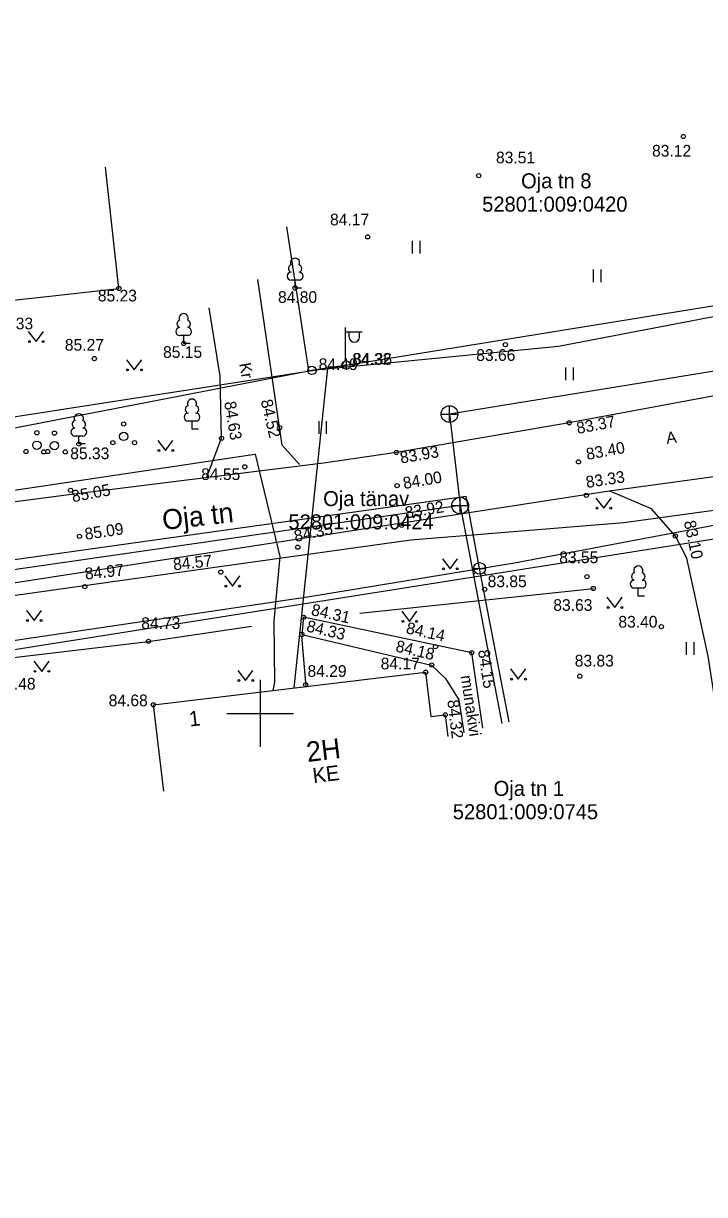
# Model space of a CAD drawing. Extents: x 648748 to 649126, y 6457789 to 6458252.
# Drawn here: x 649035.8 to 649076.6, y 6458121.2 to 6458191.3 of the extents above; entities that cross this region are included whole.
import ezdxf

# ---------------------------------------------------------------- set-up
doc = ezdxf.new("R2010")
doc.units = 0
for name, color, linetype in [('AED', 7, 'Continuous'), ('HALJASTUS', 7, 'Continuous'), ('HOONE', 7, 'Continuous'), ('KKAEV', 7, 'Continuous'), ('KORGUS-EH2000', 7, 'Continuous'), ('KTRASS', 7, 'Continuous'), ('MPOHULIIN', 7, 'Continuous'), ('PIIR', 7, 'Continuous'), ('POST', 7, 'Continuous'), ('PUU', 7, 'Continuous'), ('SITRASS', 7, 'Continuous'), ('SKTRASS', 7, 'Continuous'), ('TEE', 7, 'Continuous'), ('VKAEV', 7, 'Continuous'), ('VORK', 7, 'Continuous'), ('VTRASS', 7, 'Continuous')]:
    doc.layers.add(name, color=color, linetype=linetype)

msp = doc.modelspace()

# ---------------------------------------------------------------- linework, layer by layer
at = {"layer": 'AED'}
msp.add_line((649052.469, 6458154.613), (649052.733, 6458151.606), dxfattribs=at)
at = {"layer": 'HALJASTUS'}
for p, q in [((649059.114, 6458178.281), (649059.114, 6458177.52)), ((649059.569, 6458178.281), (649059.569, 6458177.52)), ((649069.949, 6458176.567), (649069.949, 6458175.806)), ((649070.404, 6458176.567), (649070.404, 6458175.806)), ((649036.117, 6458172.858), (649036.58, 6458172.252)), ((649036.58, 6458172.252), (649037.026, 6458172.858)), ((649042, 6458171.165), (649042.463, 6458170.558)), ((649042.463, 6458170.558), (649042.909, 6458171.165)), ((649068.287, 6458170.699), (649068.287, 6458169.938)), ((649068.742, 6458170.699), (649068.742, 6458169.938)), ((649053.508, 6458167.495), (649053.508, 6458166.734)), ((649053.963, 6458167.495), (649053.963, 6458166.734)), ((649043.871, 6458166.341), (649044.335, 6458165.734)), ((649044.335, 6458165.734), (649044.78, 6458166.341)), ((649070.112, 6458162.887), (649070.575, 6458162.281)), ((649070.575, 6458162.281), (649071.021, 6458162.887)), ((649060.913, 6458159.257), (649061.377, 6458158.651)), ((649061.377, 6458158.651), (649061.822, 6458159.257)), ((649047.879, 6458158.226), (649048.342, 6458157.619)), ((649048.342, 6458157.619), (649048.788, 6458158.226)), ((649055.967, 6458155.997), (649069.954, 6458157.476)), ((649070.772, 6458156.947), (649071.235, 6458156.341)), ((649071.235, 6458156.341), (649071.681, 6458156.947)), ((649035.999, 6458156.164), (649036.463, 6458155.557)), ((649036.463, 6458155.557), (649036.908, 6458156.164)), ((649058.48, 6458156.113), (649058.943, 6458155.506)), ((649058.943, 6458155.506), (649059.389, 6458156.113)), ((649075.514, 6458154.267), (649075.514, 6458153.506)), ((649075.969, 6458154.267), (649075.969, 6458153.506)), ((649036.454, 6458153.122), (649036.918, 6458152.516)), ((649036.918, 6458152.516), (649037.363, 6458153.122)), ((649048.663, 6458152.575), (649049.126, 6458151.968)), ((649049.126, 6458151.968), (649049.572, 6458152.575)), ((649064.997, 6458152.657), (649065.461, 6458152.051)), ((649065.461, 6458152.051), (649065.906, 6458152.657))]:
    msp.add_line(p, q, dxfattribs=at)
msp.add_lwpolyline([(649033.987, 6458147.007), (649033.538, 6458153.135), (649043.314, 6458154.31), (649049.482, 6458155.214)], dxfattribs=at)
for centre in [(649036.179, 6458172.252), (649037.008, 6458172.252), (649042.062, 6458170.558), (649042.891, 6458170.558), (649043.934, 6458165.734), (649044.763, 6458165.734), (649070.174, 6458162.281), (649071.003, 6458162.281), (649060.976, 6458158.651), (649061.805, 6458158.651), (649047.941, 6458157.619), (649048.77, 6458157.619), (649070.834, 6458156.341), (649071.663, 6458156.341), (649036.062, 6458155.557), (649036.891, 6458155.557), (649058.542, 6458155.506), (649059.371, 6458155.506), (649036.517, 6458152.516), (649037.346, 6458152.516), (649048.725, 6458151.968), (649049.554, 6458151.968), (649065.06, 6458152.051), (649065.889, 6458152.051)]:
    msp.add_circle(centre, 0.055, dxfattribs=at)
at = {"layer": 'HOONE'}
for points in [[(649023.87, 6458175.039), (649024.058, 6458173.502), (649041.542, 6458175.437), (649040.739, 6458182.695)], [(649044.224, 6458145.349), (649043.606, 6458150.514), (649059.909, 6458152.464), (649060.223, 6458149.811), (649061.086, 6458149.913), (649061.239, 6458148.619)]]:
    msp.add_lwpolyline(points, dxfattribs=at)
at = {"layer": 'KKAEV'}
for p, q in [((649060.837, 6458167.918), (649061.837, 6458167.918)), ((649061.337, 6458167.418), (649061.337, 6458168.418)), ((649061.979, 6458161.936), (649061.979, 6458162.936)), ((649061.479, 6458162.436), (649062.479, 6458162.436))]:
    msp.add_line(p, q, dxfattribs=at)
for centre in [(649061.337, 6458167.918), (649061.979, 6458162.436)]:
    msp.add_circle(centre, 0.5, dxfattribs=at)
at = {"layer": 'KORGUS-EH2000'}
for centre in [(649075.34, 6458184.531), (649063.091, 6458182.184), (649056.438, 6458178.523), (649041.542, 6458175.437), (649052.092, 6458175.457), (649045.421, 6458172.14), (649064.686, 6458172.066), (649040.074, 6458171.237), (649051.168, 6458167.094), (649068.509, 6458167.394), (649047.688, 6458166.467), (649039.143, 6458166.128), (649058.16, 6458165.62), (649069.065, 6458165.054), (649049.081, 6458164.762), (649058.204, 6458163.633), (649038.645, 6458163.351), (649069.53, 6458163.047), (649058.474, 6458161.252), (649039.177, 6458160.594), (649074.866, 6458160.615), (649052.253, 6458159.947), (649047.646, 6458158.455), (649069.575, 6458158.182), (649039.498, 6458157.587), (649063.448, 6458157.427), (649069.954, 6458157.476), (649052.605, 6458155.749), (649074.025, 6458155.193), (649052.5, 6458154.724), (649043.314, 6458154.31), (649060.5, 6458153.994), (649062.67, 6458153.626), (649059.909, 6458152.464), (649060.27, 6458152.894), (649052.724, 6458151.711), (649069.143, 6458152.223), (649043.606, 6458150.514), (649061.086, 6458149.913)]:
    msp.add_circle(centre, 0.125, dxfattribs=at)
at = {"layer": 'KTRASS'}
for p, q in [((649088.736, 6458172.365), (649061.337, 6458167.918)), ((649061.337, 6458167.918), (649061.979, 6458162.436)), ((649061.979, 6458162.436), (649028.562, 6458157.625)), ((649061.979, 6458162.436), (649064.473, 6458149.394))]:
    msp.add_line(p, q, dxfattribs=at)
at = {"layer": 'MPOHULIIN'}
msp.add_line((649054.033, 6458170.656), (649052.02, 6458151.521), dxfattribs=at)
msp.add_lwpolyline([(648949.064, 6458178.85), (648980.689, 6458168.372), (648993.115, 6458162.488), (649016.276, 6458164.81), (649054.033, 6458170.656), (649094.361, 6458177.194), (649107.677, 6458175.236)], dxfattribs=at)
at = {"layer": 'PIIR'}
for p, q in [((649052.92, 6458170.51), (649051.6, 6458179.12)), ((649090.38, 6458176.28), (649067.87, 6458171.96)), ((649067.87, 6458171.96), (649052.92, 6458170.51)), ((649017.85, 6458163.71), (649052.92, 6458170.51)), ((649032.73, 6458153.43), (649096.35, 6458163.48))]:
    msp.add_line(p, q, dxfattribs=at)
at = {"layer": 'POST'}
for p, q in [((649055.108, 6458171.092), (649055.108, 6458173.092)), ((649055.108, 6458172.842), (649056.108, 6458172.842)), ((649055.334, 6458172.521), (649055.334, 6458172.842)), ((649055.948, 6458172.521), (649055.948, 6458172.842)), ((649055.149, 6458170.845), (649053.097, 6458170.527))]:
    msp.add_line(p, q, dxfattribs=at)
for centre, radius in [((649053.097, 6458170.527), 0.25), ((649055.149, 6458170.845), 0.25), ((649055.149, 6458170.845), 0.0234), ((649053.097, 6458170.527), 0.0234)]:
    msp.add_circle(centre, radius, dxfattribs=at)
msp.add_arc((649055.641, 6458172.521), 0.306, 180, 0, dxfattribs=at)
at = {"layer": 'PUU'}
for p, q in [((649052.332, 6458175.931), (649051.852, 6458175.931)), ((649052.092, 6458175.457), (649052.092, 6458175.931)), ((649052.472, 6458175.457), (649052.092, 6458175.457)), ((649045.661, 6458172.615), (649045.181, 6458172.615)), ((649045.421, 6458172.14), (649045.421, 6458172.615)), ((649045.801, 6458172.14), (649045.421, 6458172.14)), ((649046.16, 6458167.495), (649045.68, 6458167.495)), ((649045.92, 6458167.02), (649045.92, 6458167.495)), ((649039.383, 6458166.603), (649038.903, 6458166.603)), ((649039.143, 6458166.128), (649039.143, 6458166.603)), ((649046.3, 6458167.02), (649045.92, 6458167.02)), ((649039.523, 6458166.128), (649039.143, 6458166.128)), ((649072.885, 6458157.5), (649072.405, 6458157.5)), ((649072.645, 6458157.025), (649072.645, 6458157.5)), ((649073.025, 6458157.025), (649072.645, 6458157.025))]:
    msp.add_line(p, q, dxfattribs=at)
for centre, radius in [((649041.829, 6458167.326), 0.125), ((649036.628, 6458166.798), 0.125), ((649037.682, 6458166.777), 0.125), ((649041.829, 6458166.576), 0.25), ((649035.978, 6458165.673), 0.125), ((649036.628, 6458166.048), 0.25), ((649037.032, 6458165.652), 0.125), ((649037.278, 6458165.673), 0.125), ((649037.682, 6458166.027), 0.25), ((649038.332, 6458165.652), 0.125), ((649041.179, 6458166.201), 0.125), ((649042.479, 6458166.201), 0.125)]:
    msp.add_circle(centre, radius, dxfattribs=at)
for centre, radius, start, end in [((649052.092, 6458176.976), 0.277, 332.58, 207.42), ((649051.855, 6458176.169), 0.238, 90.002, 269.395), ((649051.922, 6458176.629), 0.233, 109.022, 253.142), ((649052.262, 6458176.629), 0.233, 286.851, 70.986), ((649052.33, 6458176.169), 0.238, 270.605, 89.998), ((649045.251, 6458173.312), 0.233, 109.022, 253.142), ((649045.421, 6458173.66), 0.277, 332.58, 207.42), ((649045.591, 6458173.312), 0.233, 286.851, 70.986), ((649045.183, 6458172.852), 0.238, 90.002, 269.395), ((649045.658, 6458172.852), 0.238, 270.605, 89.998), ((649045.92, 6458168.54), 0.277, 332.58, 207.42), ((649039.143, 6458167.648), 0.277, 332.58, 207.42), ((649045.682, 6458167.732), 0.238, 90.002, 269.395), ((649045.75, 6458168.192), 0.233, 109.022, 253.142), ((649046.09, 6458168.192), 0.233, 286.851, 70.986), ((649046.157, 6458167.732), 0.238, 270.605, 89.998), ((649038.973, 6458167.301), 0.233, 109.022, 253.142), ((649039.313, 6458167.301), 0.233, 286.851, 70.986), ((649038.906, 6458166.841), 0.238, 90.002, 269.395), ((649039.381, 6458166.841), 0.238, 270.605, 89.998), ((649072.645, 6458158.545), 0.277, 332.58, 207.42), ((649072.407, 6458157.737), 0.238, 90.002, 269.395), ((649072.475, 6458158.197), 0.233, 109.022, 253.142), ((649072.815, 6458158.197), 0.233, 286.851, 70.986), ((649072.882, 6458157.737), 0.238, 270.605, 89.998)]:
    msp.add_arc(centre, radius, start, end, dxfattribs=at)
at = {"layer": 'SITRASS'}
for points in [[(649050.779, 6458151.372), (649050.885, 6458151.848), (649050.846, 6458155.528), (649051.201, 6458159.4), (649049.722, 6458165.515), (649049.686, 6458165.487), (649035.158, 6458163.312), (649030.285, 6458162.491), (649023.632, 6458161.77), (649012.724, 6458160.616), (649011.154, 6458160.421), (649010.75, 6458160.531), (649009.382, 6458168.026), (649009.225, 6458170.467), (649008.715, 6458173.607)], [(648995.643, 6458121.195), (648992.459, 6458125.184), (648989.418, 6458128.665), (648988.834, 6458130.069), (648992.568, 6458137.175), (649000.571, 6458151.371), (649010.371, 6458153.481), (649021.569, 6458155.012), (649033.911, 6458156.878), (649048.154, 6458158.873), (649059.027, 6458160.391), (649071.774, 6458161.431), (649085.639, 6458163.321), (649085.929, 6458161.874)]]:
    msp.add_lwpolyline(points, dxfattribs=at)
at = {"layer": 'SKTRASS'}
msp.add_lwpolyline([(649003.97, 6458148.61), (649015.069, 6458149.564), (649019.431, 6458150.139), (649023.183, 6458151.111), (649025.815, 6458152.505), (649033.168, 6458154.063), (649043.179, 6458155.542), (649052.834, 6458156.983), (649065.23, 6458159.005), (649081.287, 6458162.038), (649091.624, 6458163.937), (649099.708, 6458164.95)], dxfattribs=at)
at = {"layer": 'TEE'}
for points in [[(649107.397, 6458177.046), (649100.717, 6458173.988), (649091.348, 6458171.54), (649080.638, 6458169.649), (649068.509, 6458167.394), (649058.16, 6458165.62), (649053.786, 6458164.971), (649038.247, 6458163.046), (649010.385, 6458159.395), (648991.816, 6458157.612), (648986.6, 6458158.516), (648983.403, 6458159.789), (648978.499, 6458164.674), (648956.171, 6458189.218), (648949.185, 6458196.386), (648941.448, 6458204.958), (648937.194, 6458209.825), (648934.521, 6458215.407), (648934.235, 6458222.731), (648937.629, 6458230.732), (648939.834, 6458235.213)], [(649052.349, 6458164.907), (649051.323, 6458166.05), (649049.852, 6458175.962)], [(649046.781, 6458164.103), (649047.688, 6458166.467), (649047.599, 6458170.178), (649046.943, 6458174.281)], [(649002.881, 6458151.593), (649003.675, 6458152.941), (649070.906, 6458163.327), (649079.075, 6458164.441), (649081.585, 6458165.323), (649092.488, 6458167.317), (649101.716, 6458170.032), (649108.096, 6458172.531)], [(649077.28, 6458150.469), (649076.835, 6458153.415), (649075.548, 6458159.295), (649074.866, 6458160.615), (649073.445, 6458162.235), (649070.906, 6458163.327)], [(649063.339, 6458149.122), (649062.67, 6458153.626), (649052.605, 6458155.749), (649052.5, 6458154.724), (649060.27, 6458152.894), (649061.096, 6458152.089), (649061.898, 6458150.817), (649062.206, 6458148.85)]]:
    msp.add_lwpolyline(points, dxfattribs=at)
at = {"layer": 'VKAEV'}
for p, q in [((649062.794, 6458158.674), (649063.494, 6458158.674)), ((649062.897, 6458158.427), (649062.757, 6458158.287)), ((649063.392, 6458158.427), (649063.531, 6458158.287))]:
    msp.add_line(p, q, dxfattribs=at)
msp.add_circle((649063.144, 6458158.674), 0.35, dxfattribs=at)
at = {"layer": 'VORK'}
for p, q in [((649050, 6458152), (649050, 6458148)), ((649048, 6458150), (649052, 6458150))]:
    msp.add_line(p, q, dxfattribs=at)
at = {"layer": 'VTRASS'}
for points in [[(648976.302, 6458139.082), (648997.673, 6458152.175), (649000.44, 6458153.871), (649019.143, 6458157.138), (649019.466, 6458157.178), (649028.03, 6458158.241), (649030.273, 6458158.52), (649062.346, 6458163.005)], [(649064.906, 6458149.498), (649063.144, 6458158.674), (649062.346, 6458163.005)]]:
    msp.add_lwpolyline(points, dxfattribs=at)

# ---------------------------------------------------------------- texts
at = {"layer": 'HOONE'}
for s, height, p in [('1', 0.9, (649045.793, 6458149.207)), ('2H', 1.2, (649052.839, 6458147.086)), ('KE', 0.9, (649053.195, 6458145.826))]:
    msp.add_text(s, height=height, rotation=6.82039, dxfattribs=at).set_placement(p)
at = {"layer": 'KORGUS-EH2000'}
for s, p in [('83.12', (649073.471, 6458183.327)), ('83.51', (649064.123, 6458182.925)), ('84.17', (649054.186, 6458179.211)), ('85.23', (649040.279, 6458174.657)), ('84.80', (649051.069, 6458174.57)), ('85.33', (649034.063, 6458172.987)), ('85.27', (649038.304, 6458171.711)), ('85.15', (649044.184, 6458171.279)), ('84.32', (649055.515, 6458170.865)), ('84.36', (649055.556, 6458170.868)), ('83.66', (649062.942, 6458171.099)), ('84.49', (649053.504, 6458170.55)), ('85.33', (649038.627, 6458165.215)), ('84.55', (649046.469, 6458163.968)), ('83.55', (649067.911, 6458158.99)), ('83.85', (649063.622, 6458157.553)), ('83.63', (649067.556, 6458156.135)), ('84.73', (649042.878, 6458155.051)), ('83.40', (649071.453, 6458155.134)), ('84.17', (649057.218, 6458152.632)), ('83.83', (649068.84, 6458152.805)), ('84.29', (649052.835, 6458152.186)), ('85.48', (649034.21, 6458151.423)), ('84.68', (649040.928, 6458150.428))]:
    msp.add_text(s, height=0.7, dxfattribs=at).set_placement(p)
for s, rotation, p in [('84.63', 279.46232, (649047.842, 6458168.624)), ('84.52', 283.30343, (649050.03, 6458168.709)), ('83.37', 10.53444, (649069.014, 6458166.723)), ('83.93', 9.72589, (649058.438, 6458164.95)), ('83.40', 10.53444, (649069.588, 6458165.165)), ('84.00', 9.72589, (649058.617, 6458163.427)), ('83.33', 8.51399, (649069.56, 6458163.49)), ('85.05', 10.37193, (649038.779, 6458162.638)), ('83.92', 9.22132, (649058.733, 6458161.669)), ('83.10', 281.99242, (649075.371, 6458161.471)), ('85.09', 8.45196, (649039.544, 6458160.385)), ('84.35', 11.84599, (649052.11, 6458160.258)), ('84.57', 6.07935, (649044.825, 6458158.558)), ('84.97', 6.07935, (649039.538, 6458158.007)), ('84.31', 347.46412, (649053.013, 6458155.889)), ('84.33', 346.74489, (649052.727, 6458154.916)), ('84.14', 347.46412, (649058.697, 6458154.797)), ('84.18', 346.74489, (649058.068, 6458153.715)), ('84.15', 278.44995, (649063.048, 6458153.768)), ('84.32', 276.7439, (649061.209, 6458150.777))]:
    msp.add_text(s, height=0.7, rotation=rotation, dxfattribs=at).set_placement(p)
at = {"layer": 'PIIR'}
for s, rotation, p in [('Oja tn 8', 360, (649065.627, 6458181.428)), ('52801:009:0420', 360, (649063.297, 6458180.032)), ('Oja tänav', 0, (649053.774, 6458162.408)), ('52801:009:0424', 0, (649051.692, 6458161.012)), ('Oja tn 1', 0, (649063.983, 6458145.059)), ('52801:009:0745', 0, (649061.539, 6458143.663))]:
    msp.add_text(s, height=0.9, rotation=rotation, dxfattribs=at).set_placement(p)
at = {"layer": 'TEE'}
for s, height, rotation, p in [('Kr', 0.7, 280.34951, (649048.743, 6458170.926)), ('A', 0.7, 7.04935, (649074.356, 6458166.129)), ('Oja tn', 1.2, 6.43129, (649044.202, 6458160.972)), ('munakivi', 0.7, 278.44995, (649062.006, 6458152.235))]:
    msp.add_text(s, height=height, rotation=rotation, dxfattribs=at).set_placement(p)

doc.saveas('drawing.dxf')
